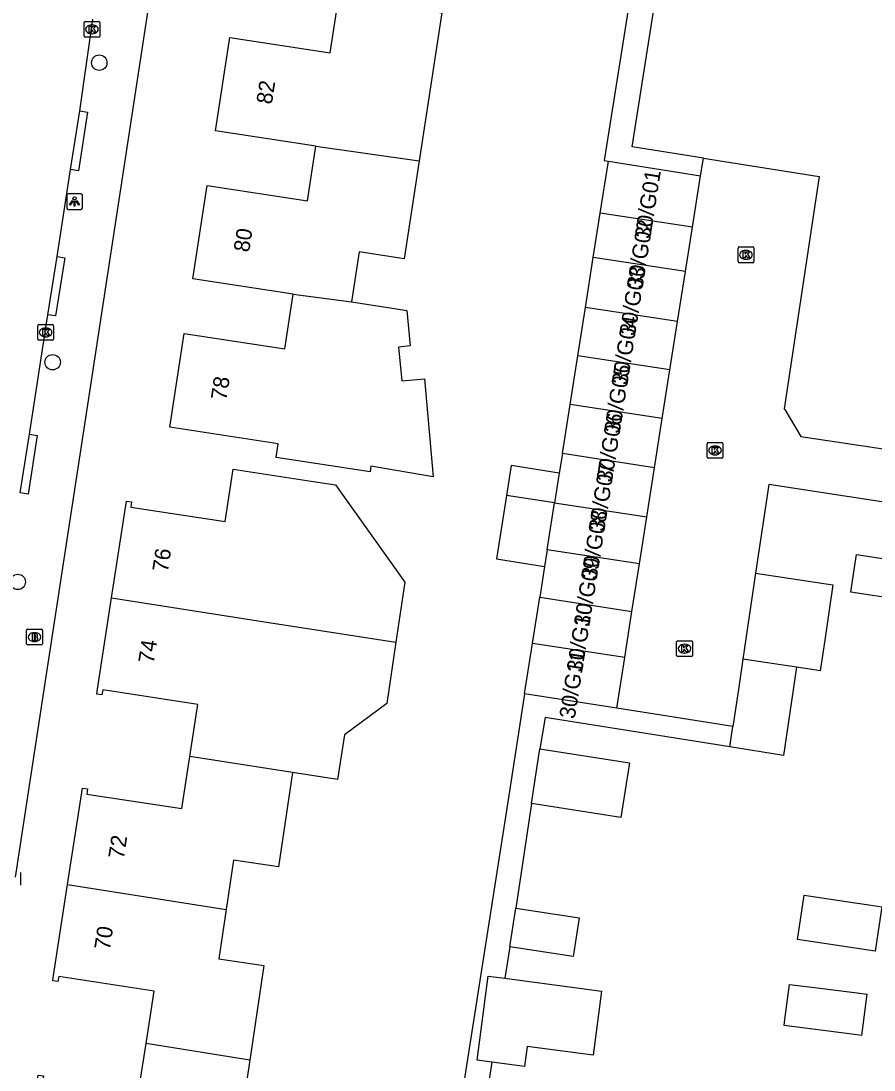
# Model space of a CAD drawing. Extents: x 161486 to 162249, y 379484 to 380829.
# Drawn here: x 161938.8 to 161992.9, y 380609.4 to 380675.9 of the extents above; entities that cross this region are included whole.
import ezdxf

# ---------------------------------------------------------------- set-up
doc = ezdxf.new("R2010")
doc.units = 0
for name, color, linetype in [('IMGEO_Boom', 7, 'Continuous'), ('IMGEO_Brandkraan', 7, 'Continuous'), ('IMGEO_Kolk', 7, 'Continuous'), ('IMGEO_Lichtpunt', 7, 'Continuous'), ('IMGEO_Pand', 7, 'Continuous'), ('IMGEO_Pand_nummerreeks', 7, 'Continuous'), ('IMGEO_Rijbaan_lokaal_open', 7, 'Continuous'), ('IMGEO_Voetpad_open', 7, 'Continuous')]:
    doc.layers.add(name, color=color, linetype=linetype)

msp = doc.modelspace()

# ---------------------------------------------------------------- linework, layer by layer
at = {"layer": 'IMGEO_Boom'}
for centre in [(161943.78, 380673.278), (161940.822, 380654.28), (161938.611, 380640.348)]:
    msp.add_circle(centre, 0.489, dxfattribs=at)
at = {"layer": 'IMGEO_Brandkraan'}
for p, q in [((161939.173, 380636.421), (161939.173, 380637.273)), ((161939.248, 380637.347), (161940.1, 380637.347)), ((161939.661, 380637.127), (161939.686, 380637.127)), ((161940.174, 380637.273), (161940.174, 380636.421)), ((161940.1, 380636.347), (161939.248, 380636.347)), ((161939.684, 380636.567), (161939.659, 380636.567))]:
    msp.add_line(p, q, dxfattribs=at)
for points in [[(161939.173, 380636.421), (161939.173, 380637.273)], [(161939.248, 380637.347), (161940.1, 380637.347)], [(161939.521, 380637.047), (161939.521, 380636.647), (161939.734, 380636.647)], [(161939.752, 380637.047), (161939.521, 380637.047)], [(161939.7, 380636.966), (161939.646, 380636.966), (161939.646, 380636.89)], [(161939.646, 380636.89), (161939.699, 380636.89)], [(161939.708, 380636.814), (161939.646, 380636.814), (161939.646, 380636.733)], [(161940.174, 380637.273), (161940.174, 380636.421)], [(161940.1, 380636.347), (161939.248, 380636.347)], [(161939.646, 380636.733), (161939.708, 380636.733)]]:
    msp.add_lwpolyline(points, dxfattribs=at)
for centre, radius, start, end in [((161939.25, 380637.271), 0.0765, 91.55205, 178.44795), ((161939.25, 380637.271), 0.0765, 91.55205, 178.44795), ((161939.701, 380636.928), 0.0379, 267.82845, 90.93552), ((161939.709, 380636.773), 0.0404, 269.87594, 90.50774), ((161939.756, 380636.902), 0.145, 59.4692, 91.53667), ((161939.781, 380636.949), 0.0922, 285.51372, 58.15012), ((161939.786, 380636.757), 0.105, 301.31148, 78.98903), ((161940.098, 380637.271), 0.0765, 1.55205, 88.44795), ((161940.098, 380637.271), 0.0765, 1.55205, 88.44795), ((161939.25, 380636.423), 0.0765, 181.55205, 268.44795), ((161939.25, 380636.423), 0.0765, 181.55205, 268.44795), ((161939.74, 380636.898), 0.251, 268.66757, 293.53466), ((161940.098, 380636.423), 0.0765, 271.55205, 358.44795), ((161940.098, 380636.423), 0.0765, 271.55205, 358.44795)]:
    msp.add_arc(centre, radius, start, end, dxfattribs=at)
for centre, major_axis, ratio, start_param, end_param in [((161939.66, 380636.847), (-0.387, 0.002), 0.722429, 4.712389, 7.853982), ((161939.685, 380636.847), (-0.39, 0.002), 0.717154, 1.570796, 4.712389)]:
    msp.add_ellipse(centre, major_axis=major_axis, ratio=ratio, start_param=start_param, end_param=end_param, dxfattribs=at)
at = {"layer": 'IMGEO_Kolk'}
for p, q in [((161942.814, 380674.967), (161942.814, 380675.819)), ((161942.889, 380675.893), (161943.741, 380675.893)), ((161943.302, 380675.673), (161943.327, 380675.673)), ((161943.815, 380675.819), (161943.815, 380674.967)), ((161943.741, 380674.893), (161942.889, 380674.893)), ((161943.325, 380675.113), (161943.3, 380675.113)), ((161984.277, 380660.665), (161984.277, 380661.517)), ((161984.352, 380661.591), (161985.204, 380661.591)), ((161984.765, 380661.371), (161984.79, 380661.371)), ((161985.278, 380661.517), (161985.278, 380660.665)), ((161984.788, 380660.811), (161984.763, 380660.811)), ((161985.204, 380660.591), (161984.352, 380660.591)), ((161939.879, 380655.743), (161939.879, 380656.595)), ((161939.954, 380656.669), (161940.806, 380656.669)), ((161940.367, 380656.449), (161940.392, 380656.449)), ((161940.88, 380656.595), (161940.88, 380655.743)), ((161940.806, 380655.669), (161939.954, 380655.669)), ((161940.39, 380655.889), (161940.365, 380655.889)), ((161982.318, 380648.26), (161982.318, 380649.112)), ((161982.393, 380649.186), (161983.245, 380649.186)), ((161982.806, 380648.966), (161982.831, 380648.966)), ((161983.319, 380649.112), (161983.319, 380648.26)), ((161983.245, 380648.186), (161982.393, 380648.186)), ((161982.829, 380648.406), (161982.804, 380648.406)), ((161980.385, 380635.69), (161980.385, 380636.542)), ((161980.46, 380636.616), (161981.312, 380636.616)), ((161980.873, 380636.396), (161980.898, 380636.396)), ((161981.386, 380636.542), (161981.386, 380635.69)), ((161981.312, 380635.616), (161980.46, 380635.616)), ((161980.896, 380635.836), (161980.871, 380635.836))]:
    msp.add_line(p, q, dxfattribs=at)
for points in [[(161942.814, 380674.967), (161942.814, 380675.819)], [(161942.889, 380675.893), (161943.741, 380675.893)], [(161943.135, 380675.593), (161943.258, 380675.593), (161943.258, 380675.442), (161943.388, 380675.593), (161943.552, 380675.593), (161943.406, 380675.442), (161943.559, 380675.193), (161943.407, 380675.193), (161943.322, 380675.357), (161943.258, 380675.29), (161943.258, 380675.193), (161943.135, 380675.193), (161943.135, 380675.593)], [(161943.815, 380675.819), (161943.815, 380674.967)], [(161943.741, 380674.893), (161942.889, 380674.893)], [(161984.277, 380660.665), (161984.277, 380661.517)], [(161984.352, 380661.591), (161985.204, 380661.591)], [(161985.278, 380661.517), (161985.278, 380660.665)], [(161984.598, 380661.291), (161984.721, 380661.291), (161984.721, 380661.14), (161984.851, 380661.291), (161985.015, 380661.291), (161984.869, 380661.14), (161985.022, 380660.891), (161984.87, 380660.891), (161984.785, 380661.055), (161984.721, 380660.988), (161984.721, 380660.891), (161984.598, 380660.891), (161984.598, 380661.291)], [(161985.204, 380660.591), (161984.352, 380660.591)], [(161939.879, 380655.743), (161939.879, 380656.595)], [(161939.954, 380656.669), (161940.806, 380656.669)], [(161940.2, 380656.369), (161940.323, 380656.369), (161940.323, 380656.218), (161940.453, 380656.369), (161940.617, 380656.369), (161940.471, 380656.218), (161940.624, 380655.969), (161940.472, 380655.969), (161940.387, 380656.133), (161940.323, 380656.066), (161940.323, 380655.969), (161940.2, 380655.969), (161940.2, 380656.369)], [(161940.88, 380656.595), (161940.88, 380655.743)], [(161940.806, 380655.669), (161939.954, 380655.669)], [(161982.318, 380648.26), (161982.318, 380649.112)], [(161982.393, 380649.186), (161983.245, 380649.186)], [(161982.639, 380648.886), (161982.762, 380648.886), (161982.762, 380648.735), (161982.892, 380648.886), (161983.056, 380648.886), (161982.91, 380648.735), (161983.063, 380648.486), (161982.911, 380648.486), (161982.826, 380648.65), (161982.762, 380648.583), (161982.762, 380648.486), (161982.639, 380648.486), (161982.639, 380648.886)], [(161983.319, 380649.112), (161983.319, 380648.26)], [(161983.245, 380648.186), (161982.393, 380648.186)], [(161980.385, 380635.69), (161980.385, 380636.542)], [(161980.46, 380636.616), (161981.312, 380636.616)], [(161980.706, 380636.316), (161980.829, 380636.316), (161980.829, 380636.165), (161980.959, 380636.316), (161981.123, 380636.316), (161980.977, 380636.165), (161981.13, 380635.916), (161980.978, 380635.916), (161980.893, 380636.08), (161980.829, 380636.013), (161980.829, 380635.916), (161980.706, 380635.916), (161980.706, 380636.316)], [(161981.386, 380636.542), (161981.386, 380635.69)], [(161981.312, 380635.616), (161980.46, 380635.616)]]:
    msp.add_lwpolyline(points, dxfattribs=at)
for centre, start, end in [((161942.891, 380675.817), 91.55205, 178.44795), ((161942.891, 380675.817), 91.55205, 178.44795), ((161943.739, 380675.817), 1.55205, 88.44795), ((161943.739, 380675.817), 1.55205, 88.44795), ((161942.891, 380674.969), 181.55205, 268.44795), ((161942.891, 380674.969), 181.55205, 268.44795), ((161943.739, 380674.969), 271.55205, 358.44795), ((161943.739, 380674.969), 271.55205, 358.44795), ((161984.354, 380661.515), 91.55205, 178.44795), ((161984.354, 380661.515), 91.55205, 178.44795), ((161985.202, 380661.515), 1.55205, 88.44795), ((161985.202, 380661.515), 1.55205, 88.44795), ((161984.354, 380660.667), 181.55205, 268.44795), ((161984.354, 380660.667), 181.55205, 268.44795), ((161985.202, 380660.667), 271.55205, 358.44795), ((161985.202, 380660.667), 271.55205, 358.44795), ((161939.956, 380656.593), 91.55205, 178.44795), ((161939.956, 380656.593), 91.55205, 178.44795), ((161940.804, 380656.593), 1.55205, 88.44795), ((161940.804, 380656.593), 1.55205, 88.44795), ((161939.956, 380655.745), 181.55205, 268.44795), ((161939.956, 380655.745), 181.55205, 268.44795), ((161940.804, 380655.745), 271.55205, 358.44795), ((161940.804, 380655.745), 271.55205, 358.44795), ((161982.395, 380649.11), 91.55205, 178.44795), ((161982.395, 380649.11), 91.55205, 178.44795), ((161983.243, 380649.11), 1.55205, 88.44795), ((161983.243, 380649.11), 1.55205, 88.44795), ((161982.395, 380648.262), 181.55205, 268.44795), ((161982.395, 380648.262), 181.55205, 268.44795), ((161983.243, 380648.262), 271.55205, 358.44795), ((161983.243, 380648.262), 271.55205, 358.44795), ((161980.462, 380636.54), 91.55205, 178.44795), ((161980.462, 380636.54), 91.55205, 178.44795), ((161981.31, 380636.54), 1.55205, 88.44795), ((161981.31, 380636.54), 1.55205, 88.44795), ((161980.462, 380635.692), 181.55205, 268.44795), ((161980.462, 380635.692), 181.55205, 268.44795), ((161981.31, 380635.692), 271.55205, 358.44795), ((161981.31, 380635.692), 271.55205, 358.44795)]:
    msp.add_arc(centre, 0.0765, start, end, dxfattribs=at)
for centre, major_axis, ratio, start_param, end_param in [((161943.301, 380675.393), (-0.387, 0.002), 0.722429, 4.712389, 7.853982), ((161943.326, 380675.393), (-0.39, 0.002), 0.717154, 1.570796, 4.712389), ((161984.764, 380661.091), (-0.387, 0.002), 0.722429, 4.712389, 7.853982), ((161984.789, 380661.091), (-0.39, 0.002), 0.717154, 1.570796, 4.712389), ((161940.366, 380656.169), (-0.387, 0.002), 0.722429, 4.712389, 7.853982), ((161940.391, 380656.169), (-0.39, 0.002), 0.717154, 1.570796, 4.712389), ((161982.805, 380648.686), (-0.387, 0.002), 0.722429, 4.712389, 7.853982), ((161982.83, 380648.686), (-0.39, 0.002), 0.717154, 1.570796, 4.712389), ((161980.872, 380636.116), (-0.387, 0.002), 0.722429, 4.712389, 7.853982), ((161980.897, 380636.116), (-0.39, 0.002), 0.717154, 1.570796, 4.712389)]:
    msp.add_ellipse(centre, major_axis=major_axis, ratio=ratio, start_param=start_param, end_param=end_param, dxfattribs=at)
at = {"layer": 'IMGEO_Lichtpunt'}
for p, q in [((161941.714, 380664.875), (161941.714, 380664.068)), ((161941.714, 380664.875), (161941.714, 380664.068)), ((161942.616, 380664.97), (161941.808, 380664.97)), ((161942.616, 380664.97), (161941.808, 380664.97)), ((161942.71, 380664.068), (161942.71, 380664.875)), ((161942.71, 380664.068), (161942.71, 380664.875)), ((161941.808, 380663.974), (161942.616, 380663.974)), ((161941.808, 380663.974), (161942.616, 380663.974)), ((161938.816, 380621.12), (161938.816, 380621.927)), ((161938.816, 380621.12), (161938.816, 380621.927))]:
    msp.add_line(p, q, dxfattribs=at)
for points in [[(161942.088, 380664.539), (161942.127, 380664.511), (161941.939, 380664.249), (161941.901, 380664.276), (161942.088, 380664.539)], [(161942.19, 380664.491), (161942.237, 380664.491), (161942.237, 380664.169), (161942.19, 380664.169), (161942.19, 380664.491)], [(161942.3, 380664.511), (161942.338, 380664.538), (161942.525, 380664.276), (161942.486, 380664.248), (161942.3, 380664.511)]]:
    msp.add_lwpolyline(points, dxfattribs=at)
msp.add_circle((161942.213, 380664.673), 0.0994, dxfattribs=at)
for centre, start, end in [((161941.808, 380664.875), 90, 180), ((161941.808, 380664.875), 90, 180), ((161942.616, 380664.875), 0, 90), ((161942.616, 380664.875), 0, 90), ((161941.808, 380664.068), 180, 270), ((161941.808, 380664.068), 180, 270), ((161942.616, 380664.068), 270, 0), ((161942.616, 380664.068), 270, 360)]:
    msp.add_arc(centre, 0.0946, start, end, dxfattribs=at)
at = {"layer": 'IMGEO_Pand'}
for points in [[(161957.517, 380667.977), (161951.146, 380668.956), (161952.055, 380674.873), (161958.426, 380673.894), (161958.957, 380677.351)], [(161962.65, 380676.871), (161965.503, 380676.432), (161964.548, 380670.232), (161964.058, 380667.043)], [(161956.075, 380658.594), (161949.704, 380659.573), (161950.613, 380665.489), (161956.984, 380664.51), (161957.517, 380667.977)], [(161957.517, 380667.977), (161964.058, 380667.043)], [(161964.058, 380667.043), (161963.101, 380660.832), (161960.248, 380661.272), (161959.762, 380658.112)], [(161975.539, 380663.742), (161976.056, 380667.027)], [(161976.056, 380667.027), (161981.895, 380666.109)], [(161981.383, 380662.851), (161981.895, 380666.109)], [(161975.096, 380660.919), (161975.539, 380663.742)], [(161981.383, 380662.851), (161975.539, 380663.742)], [(161980.939, 380660.029), (161981.383, 380662.851)], [(161974.597, 380657.748), (161975.096, 380660.919)], [(161980.939, 380660.029), (161975.096, 380660.919)], [(161980.44, 380656.858), (161980.939, 380660.029)], [(161959.762, 380658.112), (161962.615, 380657.673), (161963.272, 380657.563), (161963.499, 380655.328), (161962.743, 380655.244), (161962.971, 380653.103), (161964.393, 380653.228), (161964.942, 380647.007), (161961, 380647.692), (161960.953, 380647.327), (161954.989, 380648.242), (161955.123, 380649.113), (161953.202, 380649.409), (161948.26, 380650.17), (161949.172, 380656.106), (161955.542, 380655.127), (161956.075, 380658.594)], [(161956.075, 380658.594), (161959.762, 380658.112)], [(161974.114, 380654.678), (161974.597, 380657.748)], [(161980.44, 380656.858), (161974.597, 380657.748)], [(161979.958, 380653.787), (161980.44, 380656.858)], [(161973.631, 380651.607), (161974.114, 380654.678)], [(161979.958, 380653.787), (161974.114, 380654.678)], [(161979.475, 380650.717), (161979.958, 380653.787)], [(161973.14, 380648.483), (161973.631, 380651.607)], [(161979.475, 380650.717), (161973.631, 380651.607)], [(161978.984, 380647.592), (161979.475, 380650.717)], [(161973.14, 380648.483), (161972.947, 380647.252)], [(161978.984, 380647.592), (161973.14, 380648.483)], [(161944.558, 380639.331), (161945.5, 380645.467), (161945.827, 380645.417), (161945.777, 380645.09), (161951.767, 380644.176), (161952.275, 380647.506), (161957.216, 380646.74), (161958.758, 380646.501), (161963.157, 380640.334), (161962.59, 380636.527)], [(161972.947, 380647.252), (161969.888, 380647.732), (161969.589, 380645.828)], [(161978.493, 380644.472), (161978.984, 380647.592)], [(161972.947, 380647.252), (161972.65, 380645.362)], [(161969.589, 380645.828), (161968.958, 380641.81), (161972.016, 380641.33)], [(161972.65, 380645.362), (161969.589, 380645.828)], [(161972.183, 380642.392), (161972.65, 380645.362)], [(161972.65, 380645.362), (161978.493, 380644.472)], [(161978.026, 380641.501), (161978.493, 380644.472)], [(161972.183, 380642.392), (161972.016, 380641.33)], [(161978.026, 380641.501), (161972.183, 380642.392)], [(161991.796, 380642.083), (161996.351, 380641.381), (161996.109, 380639.804), (161996.029, 380639.285), (161995.986, 380639.003), (161991.43, 380639.703), (161991.474, 380639.986), (161991.796, 380642.083)], [(161977.551, 380638.479), (161978.026, 380641.501)], [(161972.016, 380641.33), (161971.707, 380639.37)], [(161985.388, 380640.893), (161984.579, 380635.44)], [(161985.388, 380640.893), (161990.297, 380640.165), (161989.777, 380636.657), (161989.488, 380634.71), (161988.835, 380634.809), (161987.987, 380634.935)], [(161949.527, 380629.267), (161950.033, 380632.578), (161943.997, 380633.5), (161943.947, 380633.175), (161943.622, 380633.225), (161943.67, 380633.55), (161944.558, 380639.331)], [(161944.558, 380639.331), (161954.538, 380637.779), (161962.59, 380636.527)], [(161971.248, 380636.447), (161971.707, 380639.37)], [(161971.707, 380639.37), (161977.551, 380638.479)], [(161977.091, 380635.556), (161977.551, 380638.479)], [(161962.59, 380636.527), (161962.009, 380632.631), (161959.319, 380630.638), (161958.876, 380627.806), (161956.037, 380628.25)], [(161970.745, 380633.249), (161971.248, 380636.447)], [(161977.091, 380635.556), (161971.248, 380636.447)], [(161976.584, 380632.331), (161977.091, 380635.556)], [(161984.579, 380635.44), (161984.296, 380633.533), (161983.946, 380631.174)], [(161987.987, 380634.935), (161984.579, 380635.44)], [(161987.987, 380634.935), (161987.156, 380629.341), (161983.754, 380629.884)], [(161976.584, 380632.331), (161970.745, 380633.249)], [(161983.754, 380629.884), (161983.946, 380631.174)], [(161971.712, 380629.756), (161977.391, 380628.879), (161976.855, 380625.415), (161971.177, 380626.292)], [(161971.177, 380626.292), (161971.712, 380629.756)], [(161941.769, 380621.155), (161942.71, 380627.267), (161943.037, 380627.217), (161942.987, 380626.89), (161949.023, 380625.968), (161949.527, 380629.267)], [(161956.037, 380628.25), (161949.527, 380629.267)], [(161956.037, 380628.25), (161955.146, 380622.272), (161952.29, 380622.697), (161951.825, 380619.577)], [(161946.743, 380611.081), (161947.253, 380614.401), (161941.207, 380615.33), (161941.157, 380615.005), (161940.832, 380615.055), (161940.88, 380615.38), (161941.769, 380621.155)], [(161941.769, 380621.155), (161951.825, 380619.577)], [(161988.114, 380618.063), (161988.473, 380620.472), (161991.131, 380620.075), (161992.57, 380619.86), (161993.396, 380619.737), (161992.976, 380616.926), (161988.054, 380617.662), (161988.114, 380618.063)], [(161951.825, 380619.577), (161951.359, 380616.452), (161954.215, 380616.027), (161953.318, 380610.009)], [(161970.184, 380619.651), (161974.204, 380619.038), (161973.83, 380616.581), (161969.81, 380617.194)], [(161969.81, 380617.194), (161970.184, 380619.651)], [(161968.663, 380609.885), (161967.731, 380610.008), (161968.435, 380615.347), (161969.486, 380615.208)], [(161969.486, 380615.208), (161975.628, 380614.398), (161975.092, 380610.334), (161970.91, 380610.886), (161970.742, 380609.611), (161968.663, 380609.885)], [(161987.531, 380614.823), (161989.291, 380614.6), (161991.828, 380614.278), (161992.442, 380614.2), (161992.11, 380611.587), (161991.497, 380611.665), (161987.2, 380612.211), (161987.25, 380612.605), (161987.531, 380614.823)], [(161938.975, 380602.968), (161939.91, 380609.067), (161940.237, 380609.017), (161940.187, 380608.69), (161946.233, 380607.761), (161946.743, 380611.081)], [(161953.318, 380610.009), (161946.743, 380611.081)], [(161953.318, 380610.009), (161952.424, 380604.011), (161949.568, 380604.437), (161949.104, 380601.327)]]:
    msp.add_lwpolyline(points, dxfattribs=at)
at = {"layer": 'IMGEO_Rijbaan_lokaal_open'}
for points in [[(161942.538, 380670.221), (161943.378, 380676.03)], [(161941.964, 380666.501), (161942.538, 380670.221)], [(161981.895, 380666.109), (161982.08, 380667.223)], [(161982.08, 380667.223), (161989.414, 380666.058), (161987.203, 380651.331), (161987.236, 380651.277), (161988.263, 380649.576), (162004.204, 380647.191)], [(161941.106, 380660.987), (161941.964, 380666.501)], [(161940.513, 380657.293), (161941.106, 380660.987)], [(161939.351, 380649.714), (161940.513, 380657.293)], [(161938.771, 380645.995), (161939.351, 380649.714)], [(162001.238, 380644.211), (161986.222, 380646.516), (161985.388, 380640.893)], [(161983.946, 380631.174), (161976.584, 380632.331)]]:
    msp.add_lwpolyline(points, dxfattribs=at)
at = {"layer": 'IMGEO_Voetpad_open'}
for points in [[(161955.311, 380731.889), (161949.611, 380694.604), (161942.94, 380651.025), (161940.472, 380634.904), (161938.44, 380621.627)], [(161982.08, 380667.223), (161977.569, 380667.933), (161983.609, 380706.352), (161982.278, 380706.561), (161981.795, 380706.637), (161979.804, 380693.104), (161978.273, 380682.786), (161975.782, 380667.07), (161976.056, 380667.027)], [(161942.538, 380670.221), (161943.032, 380670.145), (161942.458, 380666.425), (161941.964, 380666.501)], [(161941.106, 380660.987), (161941.599, 380660.908), (161941.006, 380657.214), (161940.513, 380657.293)], [(161939.351, 380649.714), (161939.845, 380649.637), (161939.265, 380645.918), (161938.771, 380645.995)], [(161970.745, 380633.249), (161969.705, 380626.52), (161963.937, 380589.722), (161964.224, 380587.502), (161969.225, 380582.226)], [(161983.754, 380629.884), (161972.042, 380631.754), (161971.712, 380629.756)], [(161971.177, 380626.292), (161970.184, 380619.651)], [(161969.81, 380617.194), (161969.486, 380615.208)], [(161968.663, 380609.885), (161966.698, 380597.162)]]:
    msp.add_lwpolyline(points, dxfattribs=at)

# ---------------------------------------------------------------- texts
at = {"layer": 'IMGEO_Pand_nummerreeks'}
for s, rotation, p in [('82', 81.26621, (161954.717, 380670.596)), ('30/G01', 81.0644, (161978.708, 380662.066)), ('80', 81.26476, (161953.276, 380661.219)), ('30/G02', 81.0644, (161978.212, 380658.91)), ('30/G03', 81.0644, (161977.742, 380655.92)), ('30/G04', 81.0644, (161977.251, 380652.8)), ('30/G05', 81.0644, (161976.769, 380649.729)), ('78', 81.26544, (161951.833, 380651.826)), ('30/G06', 81.0644, (161976.282, 380646.631)), ('30/G07', 81.06207, (161975.791, 380643.508)), ('30/G08', 81.0644, (161975.312, 380640.466)), ('76', 81.26974, (161948.122, 380640.927)), ('30/G09', 81.06207, (161974.84, 380637.463)), ('30/G10', 81.0644, (161974.388, 380634.588)), ('74', 81.26974, (161947.232, 380635.132)), ('30/G11', 81.0644, (161973.921, 380631.619)), ('72', 81.24804, (161945.331, 380622.731)), ('70', 81.24804, (161944.442, 380616.957))]:
    msp.add_text(s, height=1, rotation=rotation, dxfattribs=at).set_placement(p)

doc.saveas('drawing.dxf')
